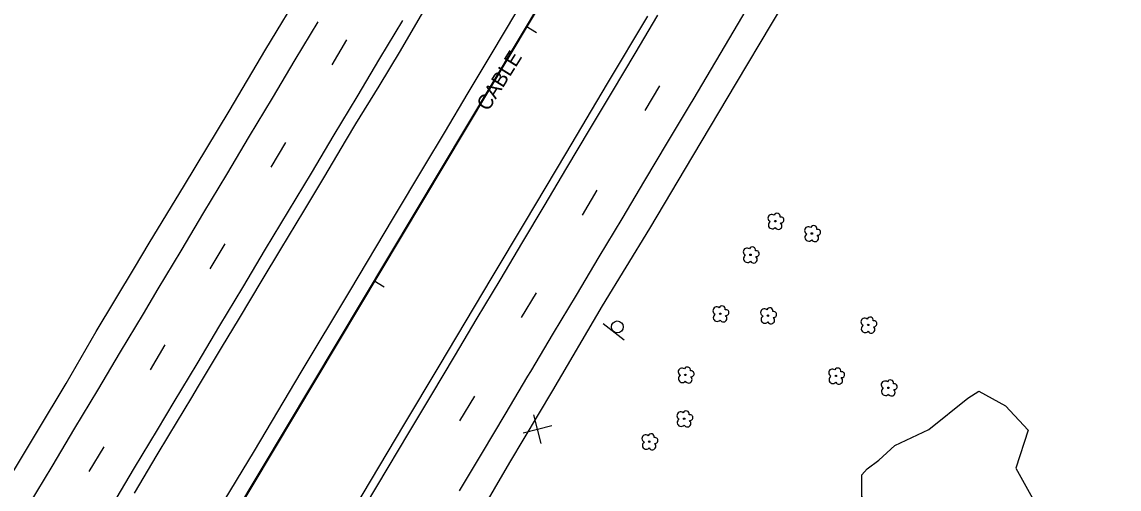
# Model space of a CAD drawing. Extents: x 2132221 to 2141942, y 535736 to 547298.
# Drawn here: x 2138558.7 to 2138928.5, y 541583.2 to 541740.8 of the extents above; entities that cross this region are included whole.
import ezdxf

# ---------------------------------------------------------------- set-up
doc = ezdxf.new("R2010")
doc.units = 0
for name, color, linetype in [('RD_EX_BldgApp', 7, 'Continuous'), ('RD_EX_DR_Pipe', 7, 'Continuous'), ('RD_EX_GuardRail', 7, 'Continuous'), ('RD_EX_GuardRail_txCode', 7, 'Continuous'), ('RD_EX_Misc', 7, 'Continuous'), ('RD_EX_Road', 7, 'Continuous'), ('RD_EX_VEG', 7, 'Continuous'), ('RD_HC_Cl', 7, 'Continuous'), ('RD_HC_Data_Tic', 7, 'Continuous')]:
    doc.layers.add(name, color=color, linetype=linetype)

msp = doc.modelspace()

# ---------------------------------------------------------------- linework, layer by layer
at = {"layer": 'RD_EX_BldgApp'}
msp.add_line((2138754.62, 541639.08), (2138761.68, 541633.5), dxfattribs=at)
msp.add_circle((2138759.42, 541637.87), 2, dxfattribs=at)
at = {"layer": 'RD_EX_DR_Pipe'}
msp.add_lwpolyline([(2138470.52, 541306.69), (2138780.46, 541825.4), (2138829.99, 541819.57)], dxfattribs=at)
at = {"layer": 'RD_EX_GuardRail'}
msp.add_lwpolyline([(2138741.42, 541771.02), (2138732.99, 541756.82), (2138725.11, 541743.68), (2138717.15, 541730.38), (2138709.08, 541716.89), (2138701.01, 541703.4), (2138694.44, 541692.3), (2138683.85, 541674.67), (2138669.13, 541649.92), (2138652.79, 541622.56), (2138636.97, 541596.05), (2138620.77, 541569.14)], dxfattribs=at)
at = {"layer": 'RD_EX_Misc'}
for p, q in [((2138663.3, 541726.34), (2138668.29, 541734.73)), ((2138768.81, 541710.85), (2138773.8, 541719.23)), ((2138642.71, 541691.75), (2138647.71, 541700.14)), ((2138747.66, 541675.61), (2138752.65, 541683.99)), ((2138622.21, 541657.5), (2138627.21, 541665.88)), ((2138727.17, 541641), (2138732.16, 541649.39)), ((2138602.06, 541623.41), (2138607.05, 541631.79)), ((2138706.39, 541606.13), (2138711.38, 541614.52)), ((2138733.79, 541598.54), (2138731.25, 541608.21)), ((2138727.68, 541602.11), (2138737.36, 541604.64)), ((2138581.44, 541589.05), (2138586.43, 541597.43))]:
    msp.add_line(p, q, dxfattribs=at)
for points in [[(2138807.74, 541753.25), (2138800.11, 541740.33), (2138792.48, 541727.41), (2138784.85, 541714.5), (2138783.97, 541713), (2138776.28, 541700.12), (2138768.59, 541687.24), (2138760.91, 541674.36), (2138753.22, 541661.48), (2138745.53, 541648.6), (2138737.85, 541635.72), (2138730.16, 541622.84), (2138729.2, 541621.23), (2138721.51, 541608.35), (2138713.83, 541595.47), (2138706.14, 541582.59)], [(2138674.54, 541577.57), (2138682.22, 541590.45), (2138689.18, 541602.13), (2138696.85, 541615.02), (2138704.53, 541627.91), (2138712.21, 541640.79), (2138719.88, 541653.68), (2138727.56, 541666.57), (2138734.75, 541678.63), (2138742.42, 541691.51), (2138750.1, 541704.4), (2138757.78, 541717.29), (2138765.45, 541730.17), (2138773.13, 541743.06)], [(2138561.17, 541577.96), (2138568.87, 541590.83), (2138576.57, 541603.71), (2138584.27, 541616.58), (2138591.97, 541629.45), (2138599.66, 541642.33), (2138604.66, 541650.69), (2138612.36, 541663.56), (2138620.06, 541676.44), (2138627.76, 541689.31), (2138635.46, 541702.19), (2138643.15, 541715.06), (2138650.85, 541727.93), (2138658.55, 541740.81)], [(2138589.03, 541577.45), (2138596.73, 541590.32), (2138604.43, 541603.19), (2138610.05, 541612.59), (2138617.76, 541625.46), (2138625.47, 541638.33), (2138633.17, 541651.19), (2138640.88, 541664.06), (2138648.58, 541676.93), (2138656.29, 541689.8), (2138664, 541702.67), (2138671.7, 541715.54), (2138679.41, 541728.41), (2138687.11, 541741.28)]]:
    msp.add_lwpolyline(points, dxfattribs=at)
at = {"layer": 'RD_EX_Road'}
for points in [[(2138914.89, 541913.44), (2138895.6, 541881.14), (2138877.5, 541850.73), (2138859.13, 541819.86), (2138837.67, 541784.01), (2138822.96, 541759.59), (2138811.33, 541740), (2138799.45, 541720.23)], [(2138548.1, 541576.55), (2138563.93, 541602.75), (2138573.59, 541618.82), (2138583.77, 541636.3), (2138596.7, 541657.83), (2138601.61, 541666.1), (2138613.51, 541685.67), (2138628.6, 541710.63), (2138640.94, 541731.58), (2138653.63, 541752.56), (2138665.67, 541772.73), (2138676.11, 541790.53), (2138687.24, 541808.93), (2138697.28, 541825.4)], [(2138596.66, 541581.78), (2138604.32, 541594.67), (2138608.22, 541601.23), (2138615.95, 541614.08), (2138618.27, 541617.93), (2138626, 541630.78), (2138632.04, 541640.8), (2138639.75, 541653.67), (2138646.02, 541664.14), (2138653.77, 541676.98), (2138660.54, 541688.2), (2138668.19, 541701.1), (2138671.3, 541706.35), (2138679.12, 541719.15), (2138686.38, 541731.02), (2138693.9, 541743.99), (2138698.01, 541751.08), (2138705.67, 541763.98), (2138712, 541774.66), (2138719.81, 541787.47), (2138724.94, 541795.88)], [(2138468.55, 541237.79), (2138481.36, 541259.3), (2138492.75, 541278.31), (2138508.8, 541304.94), (2138524.75, 541331.76), (2138540.54, 541357.96), (2138552.03, 541377.33), (2138569.58, 541406.74), (2138581.68, 541427.05), (2138605.55, 541467.18), (2138621.85, 541494.63), (2138643.05, 541530.22), (2138654.92, 541550.18), (2138673.72, 541581.7), (2138687.48, 541604.69), (2138699.32, 541624.63), (2138717.19, 541654.69), (2138728.43, 541673.42), (2138742.06, 541696.3), (2138756.14, 541719.99), (2138769.69, 541742.7)], [(2138799.45, 541720.23), (2138784.75, 541695.46), (2138770.25, 541671.08), (2138754.37, 541644.98), (2138737.52, 541616.46), (2138723.09, 541592.15), (2138708.38, 541566.79), (2138691.89, 541538.55), (2138678.14, 541515.66), (2138663.92, 541491.32), (2138648.42, 541465), (2138631.13, 541436.52), (2138618.23, 541414.77), (2138600.78, 541385.19), (2138582.53, 541355.21), (2138566.58, 541328.08), (2138552.38, 541304.72), (2138536.8, 541278.1), (2138524.81, 541258.27), (2138511.1, 541234.63)]]:
    msp.add_lwpolyline(points, dxfattribs=at)
at = {"layer": 'RD_EX_VEG'}
msp.add_lwpolyline([(2138852.89, 541567.46), (2138847.39, 541574.24), (2138841.87, 541580.63), (2138841.79, 541587.95), (2138843.6, 541590), (2138847.58, 541592.92), (2138852.98, 541597.9), (2138864.37, 541603.21), (2138877.52, 541613.84), (2138881.28, 541616.2), (2138890.32, 541611.2), (2138897.88, 541602.99), (2138893.7, 541590.26), (2138901.06, 541577.05), (2138900.41, 541570.53), (2138897.01, 541558.14), (2138894.07, 541547.67), (2138884.85, 541538.8), (2138874.45, 541538.84), (2138864.7, 541550.22)], close=True, dxfattribs=at)
for centre in [(2138812.64, 541673.55), (2138824.99, 541669.39), (2138804.31, 541662.19), (2138794.1, 541642.3), (2138810.18, 541641.68), (2138843.99, 541638.55), (2138782.37, 541621.69), (2138833.1, 541621.36), (2138850.8, 541617.32), (2138781.95, 541606.87), (2138770.17, 541599.17)]:
    msp.add_circle(centre, 0.25, dxfattribs=at)
for centre, radius, start, end in [((2138813.29, 541675.13), 1.08, 347.6166, 157.3963), ((2138811.47, 541674.59), 1.26, 49.0921, 247.3743), ((2138811.64, 541672.28), 1.32, 119.5229, 318.3992), ((2138813.69, 541672), 1.22, 209.207, 50.7449), ((2138814.6, 541673.93), 0.995, 261.4029, 104.687), ((2138823.81, 541670.43), 1.26, 49.0921, 247.3743), ((2138823.98, 541668.13), 1.32, 119.5229, 318.3992), ((2138825.64, 541670.97), 1.08, 347.6166, 157.3963), ((2138826.03, 541667.85), 1.22, 209.207, 50.7449), ((2138826.95, 541669.77), 0.995, 261.4029, 104.687), ((2138803.14, 541663.23), 1.26, 49.0921, 247.3743), ((2138803.3, 541660.92), 1.32, 119.5229, 318.3992), ((2138804.96, 541663.76), 1.08, 347.6166, 157.3963), ((2138805.35, 541660.64), 1.22, 209.207, 50.7449), ((2138806.27, 541662.57), 0.995, 261.4029, 104.687), ((2138792.92, 541643.35), 1.26, 49.0921, 247.3743), ((2138794.74, 541643.88), 1.08, 347.6166, 157.3963), ((2138796.06, 541642.69), 0.995, 261.4029, 104.687), ((2138809, 541642.72), 1.26, 49.0921, 247.3743), ((2138810.83, 541643.26), 1.08, 347.6166, 157.3963), ((2138812.14, 541642.06), 0.995, 261.4029, 104.687), ((2138793.09, 541641.04), 1.32, 119.5229, 318.3992), ((2138795.14, 541640.76), 1.22, 209.207, 50.7449), ((2138809.17, 541640.41), 1.32, 119.5229, 318.3992), ((2138811.22, 541640.13), 1.22, 209.207, 50.7449), ((2138842.82, 541639.59), 1.26, 49.0921, 247.3743), ((2138844.64, 541640.12), 1.08, 347.6166, 157.3963), ((2138845.95, 541638.93), 0.995, 261.4029, 104.687), ((2138842.98, 541637.28), 1.32, 119.5229, 318.3992), ((2138845.03, 541637), 1.22, 209.207, 50.7449), ((2138783.02, 541623.27), 1.08, 347.6166, 157.3963), ((2138781.19, 541622.73), 1.26, 49.0921, 247.3743), ((2138781.36, 541620.43), 1.32, 119.5229, 318.3992), ((2138783.41, 541620.15), 1.22, 209.207, 50.7449), ((2138784.33, 541622.07), 0.995, 261.4029, 104.687), ((2138831.93, 541622.4), 1.26, 49.0921, 247.3743), ((2138832.09, 541620.09), 1.32, 119.5229, 318.3992), ((2138833.75, 541622.93), 1.08, 347.6166, 157.3963), ((2138834.14, 541619.81), 1.22, 209.207, 50.7449), ((2138835.06, 541621.74), 0.995, 261.4029, 104.687), ((2138849.62, 541618.37), 1.26, 49.0921, 247.3743), ((2138849.79, 541616.06), 1.32, 119.5229, 318.3992), ((2138851.45, 541618.9), 1.08, 347.6166, 157.3963), ((2138852.76, 541617.71), 0.995, 261.4029, 104.687), ((2138851.84, 541615.78), 1.22, 209.207, 50.7449), ((2138782.6, 541608.45), 1.08, 347.6166, 157.3963), ((2138780.78, 541607.92), 1.26, 49.0921, 247.3743), ((2138780.94, 541605.61), 1.32, 119.5229, 318.3992), ((2138782.99, 541605.33), 1.22, 209.207, 50.7449), ((2138783.91, 541607.26), 0.995, 261.4029, 104.687), ((2138769, 541600.21), 1.26, 49.0921, 247.3743), ((2138769.17, 541597.9), 1.32, 119.5229, 318.3992), ((2138770.82, 541600.74), 1.08, 347.6166, 157.3963), ((2138771.21, 541597.62), 1.22, 209.207, 50.7449), ((2138772.13, 541599.55), 0.995, 261.4029, 104.687)]:
    msp.add_arc(centre, radius, start, end, dxfattribs=at)
at = {"layer": 'RD_HC_Cl'}
msp.add_line((2139719.79, 543396.28), (2136851.48, 538600.7), dxfattribs=at)
msp.add_arc((2137944.04, 542541.74), 972.38, 220.32405, 325.12405, dxfattribs=at)
at = {"layer": 'RD_HC_Data_Tic'}
for p, q in [((2138728.73, 541739.3), (2138732.16, 541737.25)), ((2138677.4, 541653.48), (2138680.83, 541651.43))]:
    msp.add_line(p, q, dxfattribs=at)

# ---------------------------------------------------------------- texts
at = {"layer": 'RD_EX_GuardRail_txCode'}
msp.add_text('CABLE', height=5, rotation=57.9884, dxfattribs=at).set_placement((2138715.88, 541710.39))

doc.saveas('drawing.dxf')
